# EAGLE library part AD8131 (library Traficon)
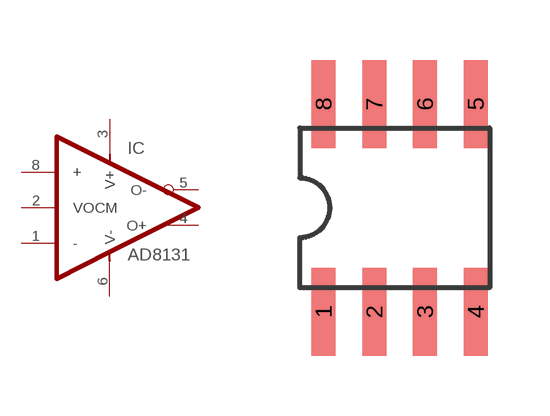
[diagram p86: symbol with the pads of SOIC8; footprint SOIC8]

Designator prefix IC

## AD8131  [SOIC8]
1  -
2  VOCM
3  V+
4  O+
5  O-
6  V-
8  +

## Footprint SOIC8 (pad centres in mm)
Small Outline IC
smd 0.6 x 2.2: 1 -1.905,-2.6; 2 -0.635,-2.6; 3 0.635,-2.6; 4 1.905,-2.6; 5 1.905,2.6; 6 0.635,2.6; 7 -0.635,2.6; 8 -1.905,2.6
